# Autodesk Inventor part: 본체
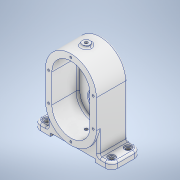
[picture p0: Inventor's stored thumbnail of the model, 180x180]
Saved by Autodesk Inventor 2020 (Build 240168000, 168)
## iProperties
Created: 2021-05
Part Number: 본체
Material: 알루미늄 6061
Document SubType Name: Modeling
Designer: Owner
Density: 2.7 g/cm^3
Appearance: 알루미늄 - 평지
Mass: 753.539 g
Surface Area: 585.808 cm^2
Volume: 279.089 cm^3
Author: Owner
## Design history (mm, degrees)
sketch "스케치1"
  geometry: L1 (-40, 22.5)-(40, 22.5); L2 (40, 22.5)-(40, -22.5); L3 (40, -22.5)-(-40, -22.5); L4 (-40, -22.5)-(-40, 22.5); L5 (-40, 22.5)-(40, -22.5); L6 (40, 22.5)-(-40, -22.5); C1 r 40 at (0, 22.5); C2 r 40 at (0, -22.5); 5 further points
  constraints: 12 end point, 4 midpoint, 2 centre point, 2 parallel, 1 horizontal, 1 perpendicular
  dimensions: "d0" = 80 distance of L2.end L3.end; "d1" = 45 distance of L1.end L2.end; "d2" = 80 diameter of C1; "d3" = 80 diameter of C2
extrude "돌출1" new body sketch "스케치1" distance "d4" = 49; taper "d5" = 0 deg
sketch "스케치2"
  geometry: L1 (-40, 22.5)-(-40, -22.5) reference; L2 (40, -22.5)-(40, 22.5) reference; L3 (30, 22.5)-(30, -22.5); L4 (-30, 22.5)-(-30, -22.5); A1 r 40 centre (0, 22.5) between (40, 22.5) and (-40, 22.5) reference; A2 r 40 centre (0, -22.5) between (-40, -22.5) and (40, -22.5) reference; A3 r 30 centre (0, 22.5) between (30, 22.5) and (-30, 22.5); A4 r 30 centre (0, -22.5) between (30, -22.5) and (-30, -22.5); 3 further points
  constraints: 4 end point, 4 point on circle, 2 centre point, 2 coincident, 2 tangent, 1 parallel
  dimensions: "d6" = 60 diameter of A3; "d7" = 60 diameter of A4
extrude "돌출2" cut sketch "스케치2" distance "d8" = 41; taper "d9" = 0 deg
sketch "스케치3"
  geometry: L1 (30, 22.5)-(30, -22.5) reference; L2 (-30, -22.5)-(-30, 22.5) reference; C1 r 14 at (0, 22.5); C2 r 14 at (0, -22.5); A1 r 30 centre (0, -22.5) between (-30, -22.5) and (30, -22.5) reference; A2 r 30 centre (0, 22.5) between (30, 22.5) and (-30, 22.5) reference; 1 further point
  constraints: 2 centre point, 2 coincident
  dimensions: "d10" = 28 diameter of C1; "d11" = 28 diameter of C2
extrude "돌출3" cut sketch "스케치3" distance "d12" = 8; taper "d13" = 0 deg
sketch "스케치6"
  geometry: L1 (40, 22.5)-(40, -22.5) reference; L2 (-40, -22.5)-(-40, 22.5) reference; L3 (-26, 22.5)-(26, 22.5); L4 (26, 22.5)-(26, -22.5); L5 (26, -22.5)-(-26, -22.5); L6 (-26, -22.5)-(-26, 22.5); L7 (-26, 22.5)-(26, -22.5); L8 (26, 22.5)-(-26, -22.5); C1 r 14 at (0, -22.5) reference; C2 r 14 at (0, 22.5) reference; C3 r 26 at (0, 22.5); C4 r 26 at (0, -22.5); A1 r 40 centre (0, 22.5) between (40, 22.5) and (-40, 22.5) reference; A2 r 40 centre (0, -22.5) between (-40, -22.5) and (40, -22.5) reference; 7 further points
  constraints: 12 end point, 3 coincident, 3 midpoint, 2 centre point, 2 parallel, 1 horizontal, 1 perpendicular
  dimensions: "d23" = 52 diameter of C3; "d24" = 52 diameter of C4; "d25" = 52 distance of L4.end L5.end; "d26" = 45 distance of L3.end L4.end
extrude "돌출5" join sketch "스케치6" distance "d27" = 8; taper "d28" = 0 deg
sketch "스케치7"
  geometry: L1 (0, 0)-(0, 15); L2 (-26, -7.5)-(26, -7.5); L3 (26, -7.5)-(26, -22.5); L4 (26, -22.5)-(-26, -22.5); L5 (-26, -22.5)-(-26, -7.5); L6 (-26, -7.5)-(26, -22.5); L7 (26, -7.5)-(-26, -22.5); L8 (-26, 22.5)-(-26, -22.5) reference; L9 (26, -22.5)-(26, 22.5) reference; A1 r 26 centre (0, -22.5) between (-26, -22.5) and (26, -22.5) reference; A2 r 26 centre (0, 22.5) between (26, 22.5) and (-26, 22.5) reference; A3 r 26 centre (0, -22.5) between (22.005, -8.652) and (21.237, -7.5); A4 r 26 centre (0, -22.5) between (-21.237, -7.5) and (-22.005, -8.652); A5 r 26 centre (0, -22.5) between (-26, -22.5) and (26, -22.5); 4 further points
  constraints: 14 end point, 6 point on circle, 3 centre point, 3 midpoint, 3 point on line, 2 coincident, 2 parallel, 1 horizontal, 1 perpendicular, 1 vertical
  dimensions: "d29" = 15 distance of L1.start L1.end; "d30" = 52 distance of L3.end L4.end; "d31" = 15 distance of L2.end L3.end
extrude "돌출6" join sketch "스케치7" distance "d33" = 3; taper "d34" = 0 deg
sketch "스케치8"
  geometry: L1 (-26, -7.5)-(26, -7.5) reference; L2 (26, -7.5)-(26, 22.5) reference; L3 (-26, 22.5)-(-26, -7.5) reference; C1 r 11 at (0, 22.5); C2 r 14 at (0, 22.5); A1 r 26 centre (0, 22.5) between (26, 22.5) and (-26, 22.5) reference; 1 further point
  constraints: 2 centre point, 2 coincident
  dimensions: "d35" = 22 diameter of C1; "d36" = 28 diameter of C2
  node "투영된 루프6"
extrude "돌출7" cut sketch "스케치8" extent not by distance; stored distance "d37" = 0; taper "d38" = 0 deg
extrude "돌출8" cut sketch "스케치8" distance "d39" = 4; taper "d40" = 0 deg
sketch "스케치9"
  geometry: C1 r 14 at (0, 0) reference; C2 r 10 at (0, 0); 1 further point
  constraints: 1 centre point, 1 coincident
  dimensions: "d41" = 20 diameter of C2
extrude "돌출9" cut sketch "스케치9" distance "d42" = 4; taper "d43" = 0 deg
node "작업 평면1"
sketch "스케치10"
  geometry: L1 (61, 0)-(-61, 0); L2 (-61, 0)-(-61, 46); L3 (-61, 46)-(61, 46); L4 (61, 46)-(61, 0); L5 (61, 0)-(-61, 46); L6 (-61, 0)-(61, 46); L7 (40, 0)-(-40, 0) reference; L8 (-40, 0)-(40, 0); L9 (40, 0)-(40, 46); L10 (40, 46)-(-40, 46); L11 (-40, 46)-(-40, 0); L12 (-40, 0)-(40, 46); L13 (40, 0)-(-40, 46); 9 further points
  constraints: 24 end point, 8 midpoint, 4 parallel, 2 horizontal, 2 perpendicular
  dimensions: "d45" = 122 distance of L2.end L3.end; "d46" = 46 distance of L1.end L2.end; "d49" = 80 distance of L9.end L10.end; "d50" = 46 distance of L8.end L9.end
extrude "돌출10" join sketch "스케치10" distance "d47" = 10; taper "d48" = 0 deg
extrude "돌출11" cut sketch "스케치10" stored distance "d51" = 10; taper "d52" = 0 deg
extrude "돌출12" join sketch "스케치10" stored distance "d53" = 10; taper "d54" = 0 deg
sketch "스케치11"
  geometry: L1 (-183.904, -47)-(-183.904, -42); L2 (-61, -37)-(-40, -37) reference; L3 (-61, -47)-(-61, -37) reference; L4 (-61, -47)-(61, -47) reference; L5 (61, -47)-(61, -37) reference; L6 (40, -37)-(61, -37) reference; L7 (40, -37)-(40, 0) reference; L8 (-40, -37)-(-40, 0) reference; L9 (-35, -42)-(35, -42); L10 (35, -42)-(35, -52); L11 (35, -52)-(-35, -52); L12 (-35, -52)-(-35, -42); L13 (61, -47)-(-61, -47) reference; L14 (-35, -42)-(35, -52); L15 (35, -42)-(-35, -52); L16 (-35, -47)-(35, -47); A1 r 40 centre (0, 0) between (-40, 0) and (40, 0) reference; 6 further points
  constraints: 16 end point, 5 midpoint, 2 parallel, 2 point on line, 1 horizontal, 1 perpendicular
  dimensions: "d57" = 70 distance of L10.end L11.end; "d59" = 5 distance between parallel lines of L9 L16
extrude "돌출13" cut sketch "스케치11" extent not by distance; stored distance "d60" = 0; taper "d61" = 0 deg
sketch "스케치12"
  geometry: 1 further point
sketch "스케치13"
  geometry: L1 (70, -46)-(0, -46) reference; L2 (70, 0)-(70, -46) reference; L3 (0, 0)-(70, 0) reference; L4 (0, 0)-(0, -46) reference; L5 (75, 0)-(-5, 0) reference; L6 (35, 0)-(35, -21); C1 r 6 at (35, -21); 2 further points
  constraints: 2 coincident, 2 end point, 1 centre point, 1 midpoint, 1 vertical
  dimensions: "d62" = 21 distance of L6.start L6.end; "d63" = 12 diameter of C1
  node "투영된 루프9"
extrude "돌출14" cut sketch "스케치13" distance "d64" = 1; taper "d65" = 0 deg
hole "구멍1" sketch "스케치13" diameter "d66" = 4.917; stored, may be unused: countersink angle "d70" = 90 deg, drill point angle "d72" = 118 deg; dims "d67" = 12, "d68" = 4, "d69" = 2, "d71" = 17.1
node "작업 평면2"
sketch "스케치14"
  geometry: C1 r 6 at (0, 25); 3 further points
  constraints: 1 centre point, 1 coincident, 1 horizontal alignment, 1 other
  dimensions: "d74" = 12 diameter of C1
extrude "돌출15" join sketch "스케치14" stored distance "d75" = 1; taper "d76" = 0 deg
sketch "스케치15"
  geometry: L1 (0, 0)-(0, 57.5); L2 (0, 0)-(0, -57.5); 2 further points
  constraints: 4 end point, 2 coincident, 2 vertical
  dimensions: "d77" = 57.5 distance of L1.start L1.end; "d78" = 57.5 distance of L1.start L2.end
hole "구멍2" sketch "스케치15" diameter "d79" = 3.242; stored, may be unused: countersink angle "d83" = 90 deg, drill point angle "d85" = 118 deg; dims "d80" = 8, "d81" = 4, "d82" = 2, "d84" = 10
hole "구멍3" sketch "스케치15" diameter "d92" = 3.242; stored, may be unused: countersink angle "d96" = 90 deg, drill point angle "d98" = 118 deg; dims "d93" = 8, "d94" = 4, "d95" = 2, "d97" = 10
fillet "모깎기1" dims "d105" = 10
sketch "스케치16"
  geometry: L1 (-40, 0)-(-51, 0) reference; L2 (-61, -10)-(-61, -36) reference; C1 r 5.5 at (-51, -10); C2 r 3.3 at (-51, -10); 1 further point
  constraints: 2 centre point, 1 coincident
  dimensions: "d106" = 11 diameter of C1; "d107" = 6.6 diameter of C2; "d108" = 10 distance from line of C1.centre L1; "d109" = 10 distance from line of C1.centre L2
extrude "돌출16" cut sketch "스케치16" distance "d110" = 2; taper "d111" = 0 deg
extrude "돌출17" cut sketch "스케치16" extent not by distance; stored distance "d112" = 0; taper "d113" = 0 deg
fillet "모깎기2" dims "d123" = 3
fillet "모깎기3" dims "d124" = 3
fillet "모깎기4" dims "d125" = 0.3
chamfer "모따기1" distance "d126" = 1; stored, may be unused: second distance "d127" = 2, angle "d128" = 45 deg
sketch "스케치17"
  geometry: L1 (0, 22.5)-(0, 42.5); C1 r 11 at (0, 22.5) reference; 2 further points
  constraints: 2 end point, 1 coincident, 1 vertical
  dimensions: "d129" = 20 distance of L1.start L1.end
hole "구멍4" sketch "스케치17" at (0, 42.5) diameter "d130" = 3.242; stored, may be unused: countersink angle "d134" = 90 deg, drill point angle "d136" = 118 deg; dims "d131" = 8, "d132" = 4, "d133" = 2, "d135" = 10
sketch "스케치18"
  geometry: L1 (23, -7.5)-(23, -22.5) reference; L2 (23, -7.5)-(-23, -7.5) reference; L3 (-23, -22.5)-(-23, -7.5) reference; L4 (-51, -62.5)-(-43, -62.5) reference; L5 (-51, -69.5)-(-51, -62.5) reference; L6 (-51, -69.5)-(-35, -69.5) reference; L7 (-35, -69.5)-(-35, -64.5) reference; L8 (-35, -64.5)-(35, -64.5) reference; L9 (35, -64.5)-(35, -69.5) reference; L10 (35, -69.5)-(51, -69.5) reference; L11 (51, -62.5)-(51, -69.5) reference; L12 (43, -62.5)-(51, -62.5) reference; L13 (37, 22.5)-(37, -56.5) reference; L14 (-37, -56.5)-(-37, 22.5) reference; L15 (-29, 22.5)-(-29, -22.5) reference; L16 (29, -22.5)-(29, 22.5) reference; L17 (0, -22.5)-(0, -59.5); L18 (-19.15, -59.5)-(19.15, -59.5); C1 r 13.7 at (0, -22.5) reference; A1 r 23 centre (0, -22.5) between (-23, -22.5) and (23, -22.5) reference; A2 r 6 centre (43, -56.5) between (37, -56.5) and (43, -62.5) reference; A3 r 37 centre (0, 22.5) between (37, 22.5) and (-37, 22.5) reference; A4 r 6 centre (-43, -56.5) between (-43, -62.5) and (-37, -56.5) reference; A5 r 29 centre (0, 22.5) between (29, 22.5) and (-29, 22.5) reference; A6 r 29 centre (0, -22.5) between (-29, -22.5) and (29, -22.5) reference; 1 further point
  constraints: 4 end point, 2 horizontal, 1 midpoint, 1 vertical
  dimensions: "d140" = 37 distance of L17.end L17.start
feature "엠보싱1" sketch "스케치18" dims "d6" = 60, "d7" = 60, "d141" = 0.5, "d142" = 0
node "솔리드1"
pattern_circular "원형 패턴1" dims angle "d87" = 90 deg
pattern_circular "원형 패턴2" dims angle "d90" = -90 deg
pattern_circular "원형 패턴3" dims angle "d100" = 90 deg
pattern_circular "원형 패턴4" dims angle "d103" = -90 deg
pattern_linear "직사각형 패턴1" dims "d116" = 26
pattern_linear "직사각형 패턴2" dims "d119" = 102
pattern_linear "직사각형 패턴3" dims "d122" = 26
pattern_circular "원형 패턴5" dims angle "d138" = 360 deg
node "투영된 루프1"
node "투영된 루프2"
node "투영된 루프4"
node "투영된 루프5"
node "투영된 루프7"
node "투영된 루프8"
node "투영된 루프10"
node "투영된 루프11"
feature "A9D066F2-1C7D-4E18-AEED-F7BC21143FA4" dims "d79" = 3.242, "d80" = 8, "d81" = 4, "d82" = 2, "d83" = 90 deg, "d84" = 10, "d85" = 118 deg
other parameters: "d32" = 52, "d44" = -69.5, "d73" = 65.5
